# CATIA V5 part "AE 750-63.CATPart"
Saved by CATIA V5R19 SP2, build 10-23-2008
Part number: AE 750-63
Bounding box of the stored display mesh (mm): x -24.865 to 24.865, y -24.997 to 24.997, z 0 to 177
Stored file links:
  C:\Users\Bora\Desktop\3D Katı model\AE serisi\AE 750\AE 750-63.CATPart
  C:\Program Files\Dassault Systemes\B19\intel_a\reffiles\standard\MetricThickPitch.txt
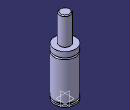
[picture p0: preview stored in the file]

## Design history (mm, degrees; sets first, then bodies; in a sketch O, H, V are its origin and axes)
Body1 (main body)
  Sketch1 on yz-plane, origin (0, 0, 0), H (0, 1, 0), V (0, 0, 1)
    point P1 (25, 96.5)
    point P8 (25, 100.5)
    point P9 (12.5, 175)
    point P11 (12.5, 175)
    point P13 (25, 100.5)
    point P14 (25, 96.5)
    line L1 (25, 96.5) -> (25, 8)
    line L2 (25, 4) -> (25, 0)
    line L3 (21.5, 8) -> (21.5, 4)
    line L4 (25, 113) -> (25, 100.5)
    line L5 (12.5, 175) -> (12.5, 113)
    arc A1 centre (10.5, 175) radius 2 from (12.5, 175) to (10.5, 177) ccw
    arc A2 centre (25, 98.5) radius 2 from (25, 100.5) to (25, 96.5) ccw
    line L6 (10.5, 177) -> (0, 177)
    point P15 (0, 177)
    line L7 (12.5, 113) -> (25, 113)
    line L8 (0, 0) -> (25, 0)
    line L9 (21.5, 8) -> (25, 8)
    line L10 (21.5, 4) -> (25, 4)
    coincidence: P15 V, P1 P14, P8 P13, P9 P11
    tangency: L6 A1
    horizontal: L7 H, L8 H, L9 H, L10 H
  Shaft1: profile Sketch1, axis Sketch1.V, angle 360
  Sketch2 on face of Shaft1 from Sketch1.L8, origin (0, 0, 0), H (1, 0, 0), V (0, -1, 0)
    point P1 (10, 0)
    distance P1 V = 10
  Hole1: placed by Sketch2, at (10, 0, 0) direction (0, 0, 1), diameter 6.647, depth 13, threaded "M8", thread diameter 8, thread depth 13, pitch 1.25
  CircPattern1: of Hole1, instances 2, angular step 180, axis from xy-plane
